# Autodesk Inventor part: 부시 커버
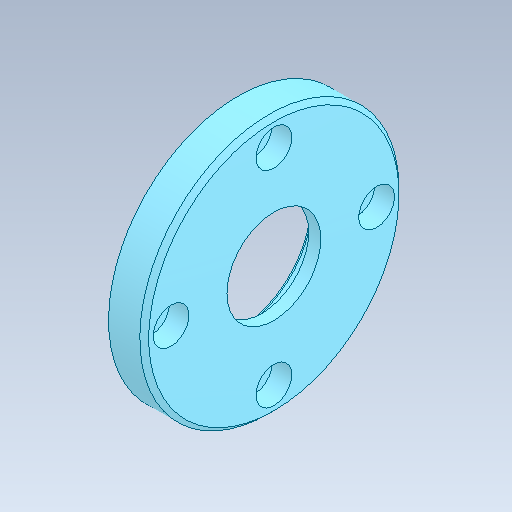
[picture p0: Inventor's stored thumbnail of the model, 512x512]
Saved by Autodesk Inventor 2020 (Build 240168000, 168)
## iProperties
Created: 2024-08
Part Number: 부시 커버
Material: 강철, 연강
Document SubType Name: Modeling
Designer: oem
Density: 7.85 g/cm^3
Appearance: 기본값
Author: jhkim
Sending System: Autodesk Inventor 2025
Preprocessor: ST-DEVELOPER v20
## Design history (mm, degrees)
node "부시 커버1"
node "솔리드2"
node "솔리드1"
